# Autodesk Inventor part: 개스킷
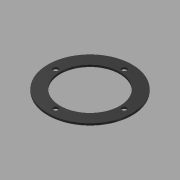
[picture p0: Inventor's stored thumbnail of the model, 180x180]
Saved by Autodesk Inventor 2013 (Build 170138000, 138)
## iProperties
Created: 2018-06
Part Number: 개스킷
Material: 고무
Document SubType Name: Modeling
Designer: G4400
Density: 1 g/cm^3
Author: G4400
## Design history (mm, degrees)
sketch "스케치1"
  geometry: C1 r 32.5 at (0, 0); C2 r 23 at (0, 0); 1 further point
  constraints: 2 centre point, 2 coincident
  dimensions: "d0" = 65 diameter of C1; "d1" = 46 diameter of C2
extrude "돌출1" new body sketch "스케치1" distance "d2" = 1.5; taper "d3" = 0 deg
sketch "스케치2" dims "d5" = 26.5
  geometry: C1 r 23 at (0, 0) reference; C2 r 32.5 at (0, 0) reference; 5 further points
  constraints: 2 vertical alignment, 1 coincident, 7 other
  dimensions: "d9" = 360 deg dimension on C1.centre point (0, 26.5) (derived)
hole "구멍1" sketch "스케치2" at (-26.5, 0), (0, -26.5), (26.5, 0) diameter "d11" = 4; stored, may be unused: countersink angle "d15" = 90 deg, drill point angle "d17" = 118 deg; dims "d12" = 6, "d13" = 4, "d14" = 2, "d16" = 8
node "솔리드1"
